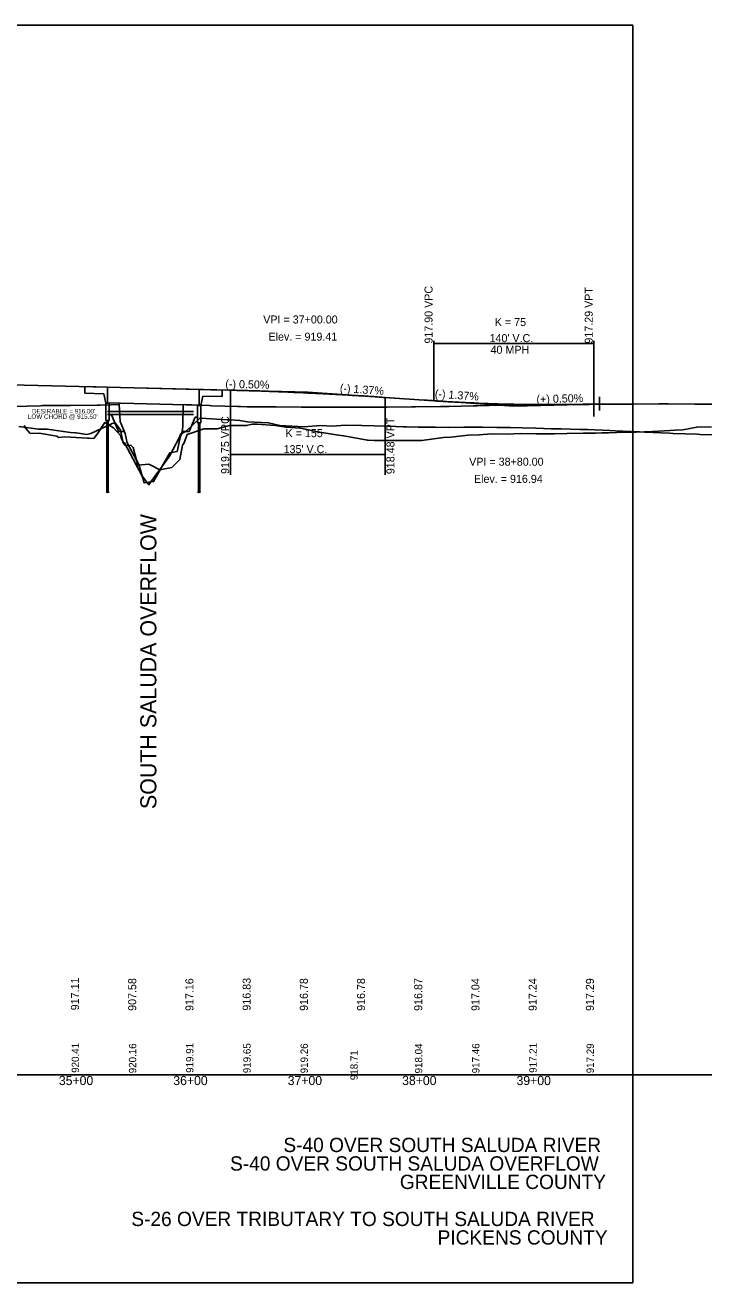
# Model space of a CAD drawing. Extents: x 1538426 to 1542651, y 1162537 to 1163637.
# Drawn here: x 1540879 to 1541472, y 1162537 to 1163637 of the extents above; entities that cross this region are included whole.
import ezdxf

# ---------------------------------------------------------------- set-up
doc = ezdxf.new("R2010")
doc.units = 0
for name, color, linetype in [('BR_CONCRETE', 7, 'Continuous'), ('BR_EXIST_GROUND_LT', 7, 'Continuous'), ('BR_EXIST_GROUND_RT', 7, 'Continuous'), ('BR_USER NOTES', 7, 'Continuous'), ('RD_DDB_GradeTX', 7, 'Continuous'), ('RD_DDB_Profile_EX', 7, 'Continuous'), ('RD_DDB_Profile_Lbl', 7, 'Continuous'), ('RD_DDB_Profile_PR', 7, 'Continuous'), ('RD_DDB_StaTX', 7, 'Continuous'), ('RD_DDB_StripGrade', 7, 'Continuous'), ('RD_DDB_VCLbl', 7, 'Continuous'), ('RD_HC_Data_Tic', 7, 'Continuous'), ('RD_SHT_ShtClip', 7, 'Continuous'), ('RD_SHT_TX', 7, 'Continuous')]:
    doc.layers.add(name, color=color, linetype=linetype)

msp = doc.modelspace()

# ---------------------------------------------------------------- linework, layer by layer
at = {"layer": 'BR_CONCRETE'}
for p, q in [((1540930.9, 1163320.6), (1540950.9, 1163320.1)), ((1540930.9, 1163314.8), (1540930.9, 1163320.6)), ((1540950.9, 1163320.1), (1541030.9, 1163318.1)), ((1540950.9, 1163320.1), (1540950.9, 1163306)), ((1541030.9, 1163318.1), (1541030.9, 1163304)), ((1541030.9, 1163318.1), (1541050.9, 1163317.6)), ((1541050.9, 1163317.6), (1541050.9, 1163311.8)), ((1540930.9, 1163314.8), (1540947.7, 1163314.4)), ((1540949.4, 1163306), (1540947.7, 1163314.4)), ((1540950.9, 1163306.4), (1541030.9, 1163304.4)), ((1541032.4, 1163304), (1541034.1, 1163312.2)), ((1541034.1, 1163312.2), (1541050.9, 1163311.8)), ((1540952.4, 1163296), (1540954.4, 1163296)), ((1540954.4, 1163296), (1540960.3, 1163281.2)), ((1540950.3, 1163291), (1540950.3, 1163228.4)), ((1540951.4, 1163291), (1540951.4, 1163228.4)), ((1541027.4, 1163294), (1541022.3, 1163281.2)), ((1541029.4, 1163294), (1541027.4, 1163294)), ((1541030.3, 1163289), (1541030.3, 1163228.4)), ((1541031.5, 1163289), (1541031.5, 1163228.4)), ((1540960.3, 1163281.2), (1540965.5, 1163281.2)), ((1541016.2, 1163281.2), (1541022.3, 1163281.2))]:
    msp.add_line(p, q, dxfattribs=at)
for points in [[(1540949.4, 1163306), (1540952.4, 1163306), (1540952.4, 1163291), (1540949.4, 1163291)], [(1541029.4, 1163304), (1541032.4, 1163304), (1541032.4, 1163289), (1541029.4, 1163289)]]:
    msp.add_lwpolyline(points, close=True, dxfattribs=at)
for points in [[(1540949.6, 1163228.4), (1540950.7, 1163228.4), (1540950.8, 1163227.8), (1540951, 1163229), (1540951.1, 1163228.4), (1540952.2, 1163228.4)], [(1541029.6, 1163228.4), (1541030.7, 1163228.4), (1541030.8, 1163227.8), (1541031, 1163229), (1541031.1, 1163228.4), (1541032.2, 1163228.4)]]:
    msp.add_lwpolyline(points, dxfattribs=at)
at = {"layer": 'BR_EXIST_GROUND_LT'}
msp.add_lwpolyline([(1540878.1, 1163286.7), (1540879.7, 1163283.6), (1540883.3, 1163279.6), (1540891.2, 1163279.8), (1540906.5, 1163277.3), (1540908.1, 1163276.1), (1540913.5, 1163276.6), (1540933.2, 1163275.5), (1540934.4, 1163275.6), (1540938.8, 1163275.3), (1540941.8, 1163279), (1540948.4, 1163289.3), (1540955.9, 1163284.5), (1540962.3, 1163277.8), (1540963.1, 1163275), (1540966, 1163269.4), (1540971.6, 1163269.1), (1540973.3, 1163267.3), (1540977.2, 1163251.8), (1540987, 1163252.7), (1540988.8, 1163251.8), (1540996.4, 1163247.7), (1541006.9, 1163249.7), (1541014, 1163256.8), (1541016.3, 1163269.3), (1541017.9, 1163271.3), (1541018.4, 1163273.1), (1541020.4, 1163278.7), (1541035, 1163283.6), (1541046.6, 1163283.8), (1541057.3, 1163286.6), (1541072.4, 1163286.6), (1541077.2, 1163287.6), (1541081.7, 1163287.6), (1541097.7, 1163286.7), (1541106.7, 1163285.1), (1541119.4, 1163284.3), (1541131.8, 1163281.5), (1541132.1, 1163281.5), (1541132.6, 1163281.4), (1541152.8, 1163278), (1541157.5, 1163277.4), (1541177.9, 1163273.7), (1541178.6, 1163273.7), (1541183.9, 1163273.5), (1541203.1, 1163273.5), (1541203.6, 1163273.5), (1541224.7, 1163273.4), (1541225.6, 1163273.4), (1541244.6, 1163276.2), (1541251, 1163276.4), (1541265.9, 1163278.2), (1541275.5, 1163278.5), (1541286.4, 1163279.2), (1541300.5, 1163278.9), (1541311.5, 1163279.5), (1541325.5, 1163279.3), (1541326.2, 1163279.3), (1541327.4, 1163279.4), (1541341.3, 1163279.4), (1541352.4, 1163279.7), (1541366.4, 1163279.8), (1541377.4, 1163280), (1541382.8, 1163280.1), (1541388.9, 1163280.2), (1541403, 1163280.7), (1541412.5, 1163280.7), (1541427, 1163281.3), (1541437.5, 1163282), (1541447, 1163282.4), (1541453.7, 1163282.9), (1541465.8, 1163285.2), (1541478.8, 1163285.5)], dxfattribs=at)
at = {"layer": 'BR_EXIST_GROUND_RT'}
msp.add_lwpolyline([(1540873.3, 1163285.6), (1540890.5, 1163283.5), (1540898.1, 1163283.3), (1540918.5, 1163280.4), (1540922.8, 1163280.3), (1540923.5, 1163280.3), (1540932.7, 1163278.8), (1540936.1, 1163279.6), (1540954.9, 1163288.2), (1540956.5, 1163288.5), (1540957.4, 1163288.9), (1540960.8, 1163284.4), (1540962.3, 1163282.6), (1540964.6, 1163271.1), (1540965.7, 1163271.4), (1540980.7, 1163242.7), (1540986.9, 1163234.7), (1540988.8, 1163237.3), (1541005, 1163259.8), (1541013.6, 1163276.4), (1541015, 1163279.4), (1541019.6, 1163281.6), (1541031.6, 1163293), (1541032.4, 1163293), (1541055.4, 1163291.5), (1541058.3, 1163291.5), (1541066.5, 1163291), (1541073.1, 1163289.9), (1541091.4, 1163288.9), (1541101.5, 1163286.7), (1541111.9, 1163286), (1541122.7, 1163285.4), (1541136.9, 1163286.5), (1541147.4, 1163286.1), (1541158.6, 1163286.8), (1541173.1, 1163286.7), (1541183.8, 1163286.2), (1541196.3, 1163286.1), (1541209.2, 1163285.4), (1541210.9, 1163285.4), (1541212.2, 1163285.3), (1541222.3, 1163285.1), (1541237.2, 1163285.2), (1541248.6, 1163284.9), (1541262.1, 1163285.1), (1541263.5, 1163285), (1541266.2, 1163285), (1541278.4, 1163285.2), (1541291.2, 1163284.7), (1541302.7, 1163284.9), (1541313.6, 1163284.4), (1541325.1, 1163284.2), (1541338.7, 1163283.8), (1541347.4, 1163283.7), (1541363.7, 1163283.2), (1541364.6, 1163283.2), (1541370.5, 1163283), (1541389.7, 1163282.1), (1541394.6, 1163282), (1541414.8, 1163280.9), (1541415.9, 1163280.9), (1541420.3, 1163280.6), (1541442.1, 1163279.9), (1541445.3, 1163279.7), (1541466.3, 1163279), (1541468.9, 1163278.8), (1541489.7, 1163278.4)], dxfattribs=at)
at = {"layer": 'BR_USER NOTES'}
for p, q in [((1541375.9, 1163320.5), (1541375.9, 1163294.4)), ((1541375.9, 1163305.2), (1541380.9, 1163305.2)), ((1541380.9, 1163311.7), (1541380.9, 1163299.8)), ((1540950.9, 1163298.7), (1541025.9, 1163298.7)), ((1540950.9, 1163296.2), (1541025.9, 1163296.2))]:
    msp.add_line(p, q, dxfattribs=at)
at = {"layer": 'RD_DDB_GradeTX'}
for p, q in [((1541045.9, 1163317.8), (1541125.9, 1163315.8)), ((1541205.7, 1163310.3), (1541125.9, 1163315.8)), ((1541226.1, 1163308.9), (1541305.9, 1163303.4)), ((1541375.9, 1163305.2), (1541305.9, 1163303.4))]:
    msp.add_line(p, q, dxfattribs=at)
at = {"layer": 'RD_DDB_Profile_EX'}
msp.add_lwpolyline([(1540868.9, 1163303.2), (1540892.3, 1163303.9), (1540893.6, 1163304), (1540917.1, 1163304.2), (1540918.6, 1163304.2), (1540941.9, 1163304.4), (1540943.6, 1163304.5), (1540944.2, 1163304.5), (1540954.1, 1163304.6), (1540960.6, 1163305), (1540961, 1163305), (1540962, 1163290.1), (1540966.2, 1163279.6), (1540968, 1163271.3), (1540978.1, 1163252.6), (1540982.7, 1163236.5), (1540988.8, 1163237.2), (1540991.1, 1163237.5), (1541005.2, 1163262.6), (1541011.6, 1163263.9), (1541013.9, 1163274.5), (1541014.3, 1163276.1), (1541016.2, 1163281), (1541016.7, 1163286.1), (1541016.9, 1163304.8), (1541039.9, 1163304), (1541041.9, 1163303.9), (1541064.6, 1163303.2), (1541066.9, 1163303.1), (1541072.6, 1163302.9), (1541073.2, 1163302.9), (1541095.6, 1163302.8), (1541098.2, 1163302.8), (1541120.2, 1163302.7), (1541123.2, 1163302.6), (1541124.1, 1163302.6), (1541131.1, 1163302.6), (1541134.3, 1163302.6), (1541156.1, 1163302.6), (1541159.4, 1163302.6), (1541181.1, 1163302.6), (1541182.6, 1163302.6), (1541191.7, 1163302.6), (1541195.2, 1163302.7), (1541216.7, 1163302.9), (1541220.1, 1163303), (1541241.7, 1163303.3), (1541248, 1163303.3), (1541249, 1163303.3), (1541270.4, 1163303.8), (1541274, 1163303.9), (1541295.1, 1163304.3), (1541299, 1163304.4), (1541315.9, 1163304.8), (1541319.4, 1163304.9), (1541340.9, 1163305), (1541344.3, 1163305), (1541366.6, 1163305.1), (1541369.3, 1163305.1), (1541381.6, 1163305.2), (1541382.8, 1163305.2), (1541385, 1163305.2), (1541407.8, 1163305.3), (1541409.8, 1163305.3), (1541432.8, 1163305.4), (1541433.3, 1163305.4), (1541439.2, 1163305.4), (1541440.9, 1163305.4), (1541464.2, 1163305.2), (1541466, 1163305.2), (1541489.2, 1163305.1)], dxfattribs=at)
at = {"layer": 'RD_DDB_Profile_PR'}
for p, q in [((1540843.4, 1163322.8), (1541058.4, 1163317.5)), ((1541193.4, 1163311.1), (1541235.9, 1163308.2))]:
    msp.add_line(p, q, dxfattribs=at)
for points in [[(1541058.4, 1163317.5), (1541061.1, 1163317.4), (1541063.8, 1163317.3), (1541066.5, 1163317.2), (1541069.2, 1163317.2), (1541071.9, 1163317.1), (1541074.6, 1163317), (1541077.3, 1163316.9), (1541080, 1163316.8), (1541082.7, 1163316.8), (1541085.4, 1163316.7), (1541088.1, 1163316.6), (1541090.8, 1163316.5), (1541093.5, 1163316.4), (1541096.2, 1163316.3), (1541098.9, 1163316.2), (1541101.6, 1163316.1), (1541104.3, 1163316), (1541107, 1163315.9), (1541109.7, 1163315.7), (1541112.4, 1163315.6), (1541115.1, 1163315.5), (1541117.8, 1163315.4), (1541120.5, 1163315.3), (1541123.2, 1163315.2), (1541125.9, 1163315), (1541128.6, 1163314.9), (1541131.3, 1163314.8), (1541134, 1163314.6), (1541136.7, 1163314.5), (1541139.4, 1163314.4), (1541142.1, 1163314.2), (1541144.8, 1163314.1), (1541147.5, 1163313.9), (1541150.2, 1163313.8), (1541152.9, 1163313.7), (1541155.6, 1163313.5), (1541158.3, 1163313.3), (1541161, 1163313.2), (1541163.7, 1163313), (1541166.4, 1163312.9), (1541169.1, 1163312.7), (1541171.8, 1163312.5), (1541174.5, 1163312.4), (1541177.2, 1163312.2), (1541179.9, 1163312), (1541182.6, 1163311.9), (1541185.3, 1163311.7), (1541188, 1163311.5), (1541190.7, 1163311.3), (1541193.4, 1163311.1)], [(1541235.9, 1163308.2), (1541238.7, 1163308), (1541241.5, 1163307.8), (1541244.3, 1163307.7), (1541247.1, 1163307.5), (1541249.9, 1163307.3), (1541252.7, 1163307.2), (1541255.5, 1163307), (1541258.3, 1163306.9), (1541261.1, 1163306.7), (1541263.9, 1163306.6), (1541266.7, 1163306.4), (1541269.5, 1163306.3), (1541272.3, 1163306.2), (1541275.1, 1163306), (1541277.9, 1163305.9), (1541280.7, 1163305.8), (1541283.5, 1163305.7), (1541286.3, 1163305.6), (1541289.1, 1163305.5), (1541291.9, 1163305.4), (1541294.7, 1163305.3), (1541297.5, 1163305.3), (1541300.3, 1163305.2), (1541303.1, 1163305.1), (1541305.9, 1163305.1), (1541308.7, 1163305), (1541311.5, 1163304.9), (1541314.3, 1163304.9), (1541317.1, 1163304.9), (1541319.9, 1163304.8), (1541322.7, 1163304.8), (1541325.5, 1163304.8), (1541328.3, 1163304.7), (1541331.1, 1163304.7), (1541333.9, 1163304.7), (1541336.7, 1163304.7), (1541339.5, 1163304.7), (1541342.3, 1163304.7), (1541345.1, 1163304.7), (1541347.9, 1163304.7), (1541350.7, 1163304.7), (1541353.5, 1163304.8), (1541356.3, 1163304.8), (1541359.1, 1163304.8), (1541361.9, 1163304.9), (1541364.7, 1163304.9), (1541367.5, 1163305), (1541370.3, 1163305), (1541373.1, 1163305.1), (1541375.9, 1163305.2)]]:
    msp.add_spline(points, degree=3, dxfattribs=at)
at = {"layer": 'RD_DDB_VCLbl'}
for p, q in [((1541235.9, 1163360.7), (1541235.9, 1163308.2)), ((1541375.9, 1163360.7), (1541375.9, 1163305.2)), ((1541235.9, 1163358.2), (1541375.9, 1163358.2)), ((1541058.4, 1163243.3), (1541058.4, 1163317.5)), ((1541193.4, 1163243.3), (1541193.4, 1163311.1)), ((1541058.4, 1163261.1), (1541193.4, 1163261.1))]:
    msp.add_line(p, q, dxfattribs=at)
at = {"layer": 'RD_HC_Data_Tic'}
msp.add_line((1538425.9, 1162718.7), (1542651.1, 1162718.7), dxfattribs=at)
at = {"layer": 'RD_SHT_ShtClip'}
for p, q in [((1539559.8, 1163636.7), (1541409.8, 1163636.7)), ((1541409.8, 1163636.7), (1541409.8, 1162536.7)), ((1541409.8, 1162536.7), (1539559.8, 1162536.7))]:
    msp.add_line(p, q, dxfattribs=at)

# ---------------------------------------------------------------- texts
at = {"layer": 'BR_USER NOTES'}
for s, p in [("LOW CHORD @ 915.50'", (1540881.2, 1163292.4)), ("DESIRABLE = 916.00'", (1540884.8, 1163297.1))]:
    msp.add_text(s, height=4, dxfattribs=at).set_placement(p)
at = {"layer": 'RD_DDB_GradeTX'}
for s, rotation, p in [('(-) 0.50%', 358.5679, (1541053.7, 1163319.6)), ('(-) 1.37%', 356.0745, (1541153.7, 1163315.9)), ('(-) 1.37%', 356.0745, (1541236.7, 1163311)), ('(+) 0.50%', 1.4321, (1541325.8, 1163306.1))]:
    msp.add_text(s, height=7, rotation=rotation, dxfattribs=at).set_placement(p)
at = {"layer": 'RD_DDB_Profile_Lbl'}
for s, p in [('VPI = 37+00.00', (1541086.9, 1163375.8)), ('Elev. = 919.41', (1541091.5, 1163360.8)), ('VPI = 38+80.00', (1541266.9, 1163251.4)), ('Elev. = 916.94', (1541271.1, 1163236.4))]:
    msp.add_text(s, height=7, dxfattribs=at).set_placement(p)
at = {"layer": 'RD_DDB_StaTX'}
for s, p in [('35+00', (1540908.3, 1162709.7)), ('36+00', (1541008.3, 1162709.7)), ('37+00', (1541108.3, 1162709.7)), ('38+00', (1541208.3, 1162709.7)), ('39+00', (1541308.3, 1162709.7))]:
    msp.add_text(s, height=8, dxfattribs=at).set_placement(p)
at = {"layer": 'RD_DDB_StripGrade'}
for s, height, p in [('917.90 VPC', 7, (1541234.9, 1163358.2)), ('917.29 VPT', 7, (1541374.9, 1163358.2)), ('919.75 VPC', 7, (1541057.1, 1163244.2)), ('918.48 VPT', 7, (1541201.6, 1163244)), ('917.11', 7, (1540925.9, 1162775.1)), ('907.58', 7, (1540975.9, 1162774.6)), ('917.16', 7, (1541025.9, 1162774.5)), ('916.83', 7, (1541075.9, 1162774.8)), ('916.78', 7, (1541125.9, 1162774.6)), ('916.78', 7, (1541175.9, 1162774.6)), ('916.87', 7, (1541225.9, 1162774.6)), ('917.04', 7, (1541275.9, 1162774.5)), ('917.24', 7, (1541325.9, 1162774.5)), ('917.29', 7, (1541375.9, 1162774.5)), ('920.41', 6.4, (1540925.9, 1162720.4)), ('920.16', 6.4, (1540975.9, 1162720)), ('919.91', 6.4, (1541025.9, 1162720.4)), ('919.65', 6.4, (1541075.9, 1162720.1)), ('919.26', 6.4, (1541125.9, 1162720)), ('918.04', 6.4, (1541225.9, 1162719.9)), ('917.46', 6.4, (1541275.9, 1162720)), ('917.21', 6.4, (1541325.9, 1162720.4)), ('917.29', 6.4, (1541375.9, 1162720)), ('918.71', 6.4, (1541169.5, 1162714))]:
    msp.add_text(s, height=height, rotation=90, dxfattribs=at).set_placement(p)
at = {"layer": 'RD_DDB_VCLbl'}
for s, p in [('K = 75', (1541289.3, 1163373.5)), ("140' V.C.", (1541284.7, 1163359.5)), ('40 MPH', (1541285.6, 1163349.3)), ('K = 155', (1541106.4, 1163276.4)), ("135' V.C.", (1541104.7, 1163262.4))]:
    msp.add_text(s, height=7, dxfattribs=at).set_placement(p)
at = {"layer": 'RD_SHT_TX'}
for s, height, rotation, p in [('SOUTH SALUDA OVERFLOW', 14, 90, (1540993.5, 1162951.1)), ('S-40 OVER SOUTH SALUDA RIVER', 12.499, 360, (1541104.5, 1162651.1)), ('S-40 OVER SOUTH SALUDA OVERFLOW', 12.499, 360, (1541057.9, 1162634.9)), ('GREENVILLE COUNTY', 12.499, 360, (1541206.3, 1162618.8)), ('S-26 OVER TRIBUTARY TO SOUTH SALUDA RIVER', 12.499, 360, (1540971.6, 1162586.4)), ('PICKENS COUNTY', 12.499, 360, (1541239.3, 1162570.2))]:
    msp.add_text(s, height=height, rotation=rotation, dxfattribs=at).set_placement(p)

doc.saveas('drawing.dxf')
